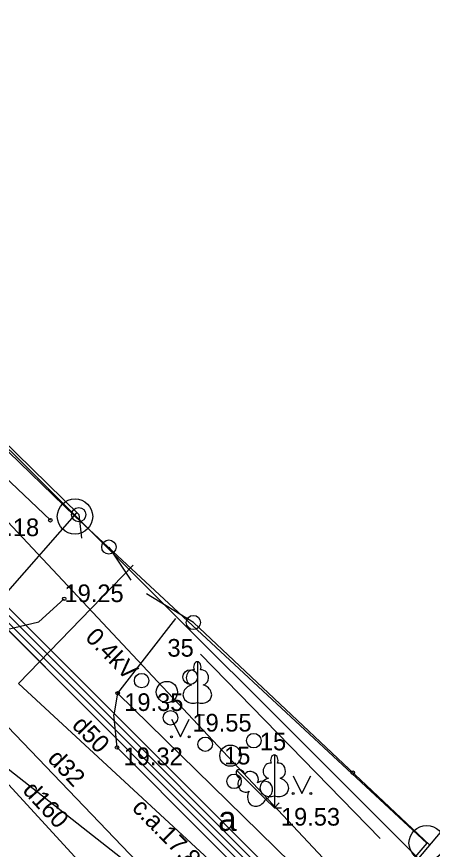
# Model space of a CAD drawing. Extents: x 532933 to 533143, y 328014 to 328163.
# Drawn here: x 533019.24 to 533031, y 328126.98 to 328150.56 of the extents above; entities that cross this region are included whole.
import ezdxf

# ---------------------------------------------------------------- set-up
doc = ezdxf.new("R2010")
doc.units = 0
for name, color, linetype in [('APGR_ELEM_####_####_#', 7, 'Continuous'), ('APGR_SARK_####_####_#', 7, 'Continuous'), ('APGS_VADV_ZSPR_####_#', 7, 'Continuous'), ('APGS_VADV_ZSPR_TKST_#', 7, 'Continuous'), ('CELI_CAPM_####_####_#', 7, 'Continuous'), ('CELI_CMAL_####_####_#', 7, 'Continuous'), ('CELI_CSEG_####_TKST_#', 7, 'Continuous'), ('ELEK_ACRL_####_####_#', 7, 'Continuous'), ('ELEK_VADP_ZSPR_####_#', 7, 'Continuous'), ('NORB_ELEM_####_####_#', 7, 'Continuous'), ('NORB_ZOGS_BARJ_####_#', 7, 'Continuous'), ('NORB_ZOGS_ZBET_####_#', 7, 'Continuous'), ('NORB_ZOGS_ZSTP_####_#', 7, 'Continuous'), ('RAMI_UZMR_####_####_#', 7, 'Continuous'), ('RELJ_AATZ_####_TKST_#', 7, 'Continuous'), ('RELJ_ELEM_####_####_#', 7, 'Continuous'), ('ROBZ_PROJ_####_####_#', 7, 'Continuous'), ('SAKT_VADV_PKAB_####_#', 7, 'Continuous'), ('TERT_DIAM_####_TKST_#', 7, 'Continuous'), ('TERT_ELEM_####_####_#', 7, 'Continuous'), ('TERT_KRND_####_####_#', 7, 'Continuous'), ('UDTK_VADP_UDEN_####_#', 7, 'Continuous'), ('UDTK_VADP_UDEN_TKST_#', 7, 'Continuous')]:
    doc.layers.add(name, color=color, linetype=linetype)

msp = doc.modelspace()

# ---------------------------------------------------------------- linework, layer by layer
at = {"layer": 'APGR_ELEM_####_####_#'}
for centre in [(533020.89, 328136.408), (533030.84, 328127.16)]:
    msp.add_circle(centre, 0.5, dxfattribs=at)
at = {"layer": 'APGR_SARK_####_####_#'}
for p, q in [((533005.074, 328151.787), (533020.89, 328136.408)), ((533020.89, 328136.408), (533030.84, 328127.16)), ((533030.84, 328127.16), (533029.49, 328125.584))]:
    msp.add_line(p, q, dxfattribs=at)
at = {"layer": 'APGS_VADV_ZSPR_####_#'}
msp.add_line((533015.099, 328140.4), (533035.157, 328119.006), dxfattribs=at)
at = {"layer": 'CELI_CAPM_####_####_#'}
for points in [[(533003.508, 328149.901), (533003.446, 328149.174), (533003.651, 328148.102), (533011.568, 328140.209), (533018.793, 328133.17), (533019.865, 328133.427), (533020.585, 328134.078)], [(533028.217, 328124.396), (533027.054, 328124.874), (533022.08, 328129.865), (533021.985, 328130.79)]]:
    msp.add_lwpolyline(points, dxfattribs=at)
at = {"layer": 'CELI_CMAL_####_####_#'}
msp.add_line((533018.988, 328134.285), (533020.941, 328136.515), dxfattribs=at)
for points in [[(533023.73, 328133.519), (533022.097, 328131.401), (533028.789, 328124.846), (533029.878, 328125.681)], [(533022.097, 328131.401), (533021.985, 328130.79)]]:
    msp.add_lwpolyline(points, dxfattribs=at)
at = {"layer": 'ELEK_ACRL_####_####_#'}
for points in [[(533021.413, 328130.777), (533011.016, 328141.172), (533009.114, 328144.174), (533001.721, 328152.298), (533000.9, 328153.335)], [(533021.501, 328130.901), (533011.134, 328141.266), (533009.234, 328144.265), (533001.836, 328152.395), (533001.035, 328153.406)], [(533021.59, 328131.025), (533011.252, 328141.36), (533009.354, 328144.357), (533001.95, 328152.493), (533001.174, 328153.479)], [(533021.678, 328131.149), (533011.37, 328141.454), (533009.474, 328144.448), (533002.065, 328152.59), (533001.306, 328153.548)]]:
    msp.add_lwpolyline(points, dxfattribs=at)
at = {"layer": 'ELEK_VADP_ZSPR_####_#'}
for p, q in [((533011.252, 328141.36), (533021.59, 328131.025)), ((533011.37, 328141.454), (533021.678, 328131.149)), ((533011.016, 328141.172), (533021.413, 328130.777)), ((533011.134, 328141.266), (533021.501, 328130.901)), ((533021.59, 328131.025), (533037.205, 328115.414)), ((533021.678, 328131.149), (533037.401, 328115.43)), ((533021.413, 328130.777), (533036.815, 328115.38)), ((533021.501, 328130.901), (533037.01, 328115.397))]:
    msp.add_line(p, q, dxfattribs=at)
at = {"layer": 'NORB_ELEM_####_####_#'}
for centre in [(533020.996, 328136.461), (533021.848, 328135.543), (533024.24, 328133.406)]:
    msp.add_circle(centre, 0.202, dxfattribs=at)
at = {"layer": 'NORB_ZOGS_BARJ_####_#'}
for p, q in [((533020.996, 328136.461), (533021.074, 328135.791)), ((533021.848, 328135.543), (533022.465, 328134.606)), ((533024.24, 328133.406), (533022.914, 328134.219))]:
    msp.add_line(p, q, dxfattribs=at)
at = {"layer": 'NORB_ZOGS_ZBET_####_#'}
msp.add_line((533029.846, 328125.831), (533031.231, 328127.46), dxfattribs=at)
at = {"layer": 'NORB_ZOGS_ZSTP_####_#'}
msp.add_line((533030.925, 328127.1), (533024.24, 328133.406), dxfattribs=at)
msp.add_lwpolyline([(533020.996, 328136.461), (533013.046, 328144.246), (533005.031, 328151.966), (533005.896, 328152.718)], dxfattribs=at)
at = {"layer": 'RAMI_UZMR_####_####_#'}
msp.add_lwpolyline([(532947.854, 328059.458), (532970.012, 328105.269), (532980.164, 328130.66), (532983.041, 328140.509), (533003.397, 328153.917), (533034.71, 328122.623), (533045.001, 328112.629), (533020.332, 328088.009), (533039.378, 328069.977), (533029.682, 328029.753), (533016.724, 328021.343), (532947.854, 328059.458)], dxfattribs=at)
at = {"layer": 'RELJ_ELEM_####_####_#'}
for centre in [(533020.193, 328136.302), (533020.585, 328134.078), (533022.097, 328131.401), (533022.08, 328129.866), (533028.75, 328129.152)]:
    msp.add_circle(centre, 0.05, dxfattribs=at)
at = {"layer": 'ROBZ_PROJ_####_####_#'}
for p, q in [((533005.074, 328151.787), (533020.89, 328136.408)), ((533020.89, 328136.408), (533030.84, 328127.16)), ((533030.84, 328127.16), (533029.49, 328125.584))]:
    msp.add_line(p, q, dxfattribs=at)
at = {"layer": 'SAKT_VADV_PKAB_####_#'}
msp.add_lwpolyline([(533043.676, 328109.828), (532992.415, 328150.168)], dxfattribs=at)
at = {"layer": 'TERT_ELEM_####_####_#'}
for p, q in [((533024.352, 328131.142), (533024.352, 328130.795)), ((533024.352, 328130.795), (533024.552, 328130.795)), ((533023.622, 328130.672), (533023.872, 328130.172)), ((533023.872, 328130.172), (533024.122, 328130.672)), ((533027.062, 328129.065), (533027.312, 328128.565)), ((533027.312, 328128.565), (533027.562, 328129.065)), ((533026.284, 328128.4), (533026.53, 328128.155)), ((533026.53, 328128.501), (533026.53, 328128.155)), ((533026.53, 328128.155), (533026.671, 328128.296)), ((533026.53, 328128.155), (533026.73, 328128.155))]:
    msp.add_line(p, q, dxfattribs=at)
for points in [[(533024.352, 328132.295), (533024.352, 328131.142)], [(533024.441, 328132.063), (533024.44, 328132.064)], [(533026.53, 328129.654), (533026.53, 328128.501)], [(533026.619, 328129.422), (533026.618, 328129.423)], [(533025.469, 328129.215), (533026.284, 328128.4)], [(533025.697, 328129.114), (533025.695, 328129.114)]]:
    msp.add_lwpolyline(points, dxfattribs=at)
for centre, radius in [((533022.775, 328131.761), 0.204), ((533024.15, 328131.862), 0.207), ((533023.489, 328131.437), 0.301), ((533023.592, 328130.709), 0.205), ((533025.949, 328130.061), 0.207), ((533023.622, 328130.171), 0.028), ((533024.122, 328130.171), 0.0263), ((533024.574, 328129.96), 0.204), ((533025.288, 328129.636), 0.301), ((533025.391, 328128.909), 0.205), ((533027.062, 328128.564), 0.028), ((533027.562, 328128.564), 0.0263)]:
    msp.add_circle(centre, radius, dxfattribs=at)
for centre, major_axis, ratio, start_param, end_param in [((533024.352, 328132.145), (0, -0.15), 0.707107, 3.14537, 5.287485), ((533024.351, 328132.145), (0, -0.15), 0.707107, 0.995701, 3.137816), ((533024.224, 328131.851), (-0.039, -0.212), 0.861323, 3.141593, 6.283185), ((533024.48, 328131.851), (0.039, -0.212), 0.861323, 0, 3.141593), ((533024.262, 328131.388), (0.307, 0.095), 0.814445, 1.570796, 4.752015), ((533024.441, 328131.388), (-0.307, 0.095), 0.814445, 1.531171, 4.712389), ((533026.53, 328129.505), (0, -0.15), 0.707107, 3.14537, 5.287485), ((533026.529, 328129.505), (0, -0.15), 0.707107, 0.995701, 3.137816), ((533026.401, 328129.21), (-0.039, -0.212), 0.861323, 3.141593, 6.283185), ((533026.658, 328129.21), (0.039, -0.212), 0.861323, 0, 3.141593), ((533025.575, 328129.109), (0.106, -0.106), 0.707107, 3.14537, 5.287485), ((533025.575, 328129.109), (0.106, -0.106), 0.707107, 0.995701, 3.137816), ((533025.874, 328128.991), (0.178, -0.123), 0.861323, 0, 3.141593), ((533025.693, 328128.81), (0.123, -0.178), 0.861323, 3.141593, 6.283185), ((533026.174, 328128.637), (-0.284, -0.15), 0.814445, 1.531171, 4.712389), ((533026.44, 328128.747), (0.307, 0.095), 0.814445, 1.570796, 4.752015), ((533026.619, 328128.747), (-0.307, 0.095), 0.814445, 1.531171, 4.712389), ((533026.047, 328128.51), (0.15, 0.284), 0.814445, 1.570796, 4.752015)]:
    msp.add_ellipse(centre, major_axis=major_axis, ratio=ratio, start_param=start_param, end_param=end_param, dxfattribs=at)
at = {"layer": 'TERT_KRND_####_####_#'}
for p, q in [((533020.193, 328136.302), (533004.117, 328151.633)), ((533024.443, 328132.508), (533029.527, 328127.294))]:
    msp.add_line(p, q, dxfattribs=at)
at = {"layer": 'UDTK_VADP_UDEN_####_#'}
msp.add_line((533009.846, 328138.784), (533026.302, 328120.883), dxfattribs=at)
for points in [[(533010.744, 328081.458), (533040.624, 328109.383), (533024.808, 328124.378), (533000, 328150.276)], [(533028.561, 328123.095), (533019.29, 328131.682), (533022.54, 328135.026)]]:
    msp.add_lwpolyline(points, dxfattribs=at)

# ---------------------------------------------------------------- texts
at = {"layer": 'APGS_VADV_ZSPR_TKST_#'}
msp.add_text('0.4kV', height=0.5, rotation=314.882, dxfattribs=at).set_placement((533021.153, 328132.956))
at = {"layer": 'CELI_CSEG_####_TKST_#'}
msp.add_text('a', height=0.7, dxfattribs=at).set_placement((533024.939, 328127.505))
at = {"layer": 'RELJ_AATZ_####_TKST_#'}
for s, p in [(' 19.18', (533018.017, 328135.852)), (' 19.25', (533020.407, 328133.984)), (' 19.35', (533022.097, 328130.901)), (' 19.55', (533024.027, 328130.319)), (' 19.32', (533022.08, 328129.366)), (' 19.53', (533026.53, 328127.655))]:
    msp.add_text(s, height=0.5, dxfattribs=at).set_placement(p)
at = {"layer": 'TERT_DIAM_####_TKST_#'}
for s, p in [('35', (533023.506, 328132.439)), ('15', (533026.121, 328129.787)), ('15', (533025.108, 328129.386))]:
    msp.add_text(s, height=0.5, dxfattribs=at).set_placement(p)
at = {"layer": 'UDTK_VADP_UDEN_TKST_#'}
for s, rotation, p in [('d50', 314.3186, (533020.777, 328130.466)), ('d32', 313.7688, (533020.088, 328129.522)), ('d160', 312.5917, (533019.383, 328128.631)), ('c.a.17.85', 314.3186, (533022.474, 328128.13))]:
    msp.add_text(s, height=0.5, rotation=rotation, dxfattribs=at).set_placement(p)

doc.saveas('drawing.dxf')
